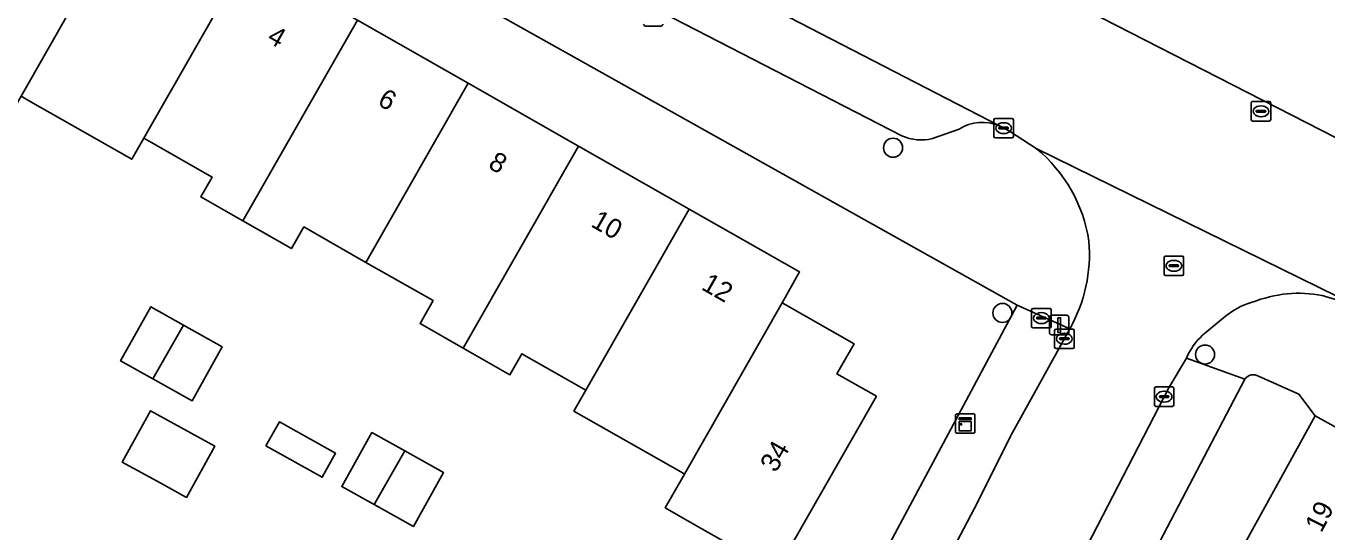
# Model space of a CAD drawing. Extents: x 160349 to 161355, y 381727 to 382854.
# Drawn here: x 160948.1 to 161014.9, y 382260.6 to 382286.6 of the extents above; entities that cross this region are included whole.
import ezdxf

# ---------------------------------------------------------------- set-up
doc = ezdxf.new("R2010")
doc.units = 0
for name, color, linetype in [('IMGEO_Boom', 7, 'Continuous'), ('IMGEO_Brandkraan', 7, 'Continuous'), ('IMGEO_Erf', 7, 'Continuous'), ('IMGEO_Kast', 7, 'Continuous'), ('IMGEO_Kolk', 7, 'Continuous'), ('IMGEO_Lichtmast', 7, 'Continuous'), ('IMGEO_Pand', 7, 'Continuous'), ('IMGEO_Pand_nummerreeks', 7, 'Continuous'), ('IMGEO_Parkeervlak_open', 7, 'Continuous'), ('IMGEO_Rijbaan_lokaal_open', 7, 'Continuous'), ('IMGEO_Rioolput', 7, 'Continuous'), ('IMGEO_Voetpad_open', 7, 'Continuous')]:
    doc.layers.add(name, color=color, linetype=linetype)

msp = doc.modelspace()

# ---------------------------------------------------------------- linework, layer by layer
at = {"layer": 'IMGEO_Boom'}
for centre in [(160992.651, 382280.362), (160998.268, 382271.874), (161008.67, 382269.741)]:
    msp.add_circle(centre, 0.489, dxfattribs=at)
at = {"layer": 'IMGEO_Brandkraan'}
for p, q in [((160999.843, 382272.112), (161000.695, 382272.112)), ((160999.768, 382271.186), (160999.768, 382272.038)), ((161000.027, 382271.606), (161000.027, 382271.618)), ((161000.465, 382271.569), (161000.067, 382271.569)), ((161000.07, 382271.655), (161000.468, 382271.655)), ((161000.256, 382271.892), (161000.281, 382271.892)), ((161000.511, 382271.618), (161000.511, 382271.606)), ((161000.769, 382272.038), (161000.769, 382271.186)), ((161000.695, 382271.112), (160999.843, 382271.112)), ((161000.279, 382271.332), (161000.254, 382271.332))]:
    msp.add_line(p, q, dxfattribs=at)
for points in [[(160999.843, 382272.112), (161000.695, 382272.112)], [(160999.768, 382271.186), (160999.768, 382272.038)], [(161000.769, 382272.038), (161000.769, 382271.186)], [(161000.695, 382271.112), (160999.843, 382271.112)]]:
    msp.add_lwpolyline(points, dxfattribs=at)
for centre, radius, start, end in [((160999.845, 382272.036), 0.0765, 91.55205, 178.44795), ((160999.845, 382272.036), 0.0765, 91.55205, 178.44795), ((161000.693, 382272.036), 0.0765, 1.55205, 88.44795), ((161000.693, 382272.036), 0.0765, 1.55205, 88.44795), ((161000.067, 382271.615), 0.0403, 85.87752, 175.75265), ((161000.064, 382271.605), 0.0366, 178.93798, 274.71019), ((161000.468, 382271.612), 0.043, 264.86636, 352.45326), ((161000.472, 382271.617), 0.0386, 1.73085, 96.63898), ((160999.845, 382271.188), 0.0765, 181.55205, 268.44795), ((160999.845, 382271.188), 0.0765, 181.55205, 268.44795), ((161000.693, 382271.188), 0.0765, 271.55205, 358.44795), ((161000.693, 382271.188), 0.0765, 271.55205, 358.44795)]:
    msp.add_arc(centre, radius, start, end, dxfattribs=at)
for centre, major_axis, ratio, start_param, end_param in [((161000.255, 382271.612), (-0.387, 0.002), 0.722429, 4.712389, 7.853982), ((161000.28, 382271.612), (-0.39, 0.002), 0.717154, 1.570796, 4.712389)]:
    msp.add_ellipse(centre, major_axis=major_axis, ratio=ratio, start_param=start_param, end_param=end_param, dxfattribs=at)
at = {"layer": 'IMGEO_Erf'}
for points in [[(160983.76, 382243.716), (160987.119, 382250), (160999.031, 382272.284), (160967.843, 382289.749), (160946.666, 382301.996), (160939.201, 382288.699), (160936.619, 382290.081), (160913.893, 382250), (160899.959, 382225.424), (160914.904, 382214.884), (160933.74, 382199.155), (160940.193, 382193.026), (160947.35, 382185.726), (160952.971, 382178.985), (160954.398, 382178.232)], [(160965.164, 382286.918), (160970.838, 382283.684), (160976.513, 382280.449), (160982.187, 382277.214), (160987.859, 382273.981), (160986.96, 382272.4), (160990.653, 382270.295), (160989.775, 382268.754), (160991.8, 382267.599), (160986.674, 382258.608), (160982.331, 382261.085), (160980.956, 382261.869), (160981.943, 382263.601), (160981.755, 382263.708), (160976.27, 382266.835), (160976.882, 382267.909), (160976.757, 382267.98), (160973.603, 382269.778), (160972.988, 382268.699), (160970.593, 382270.064), (160968.371, 382271.331), (160969.041, 382272.507), (160965.588, 382274.475), (160962.403, 382276.291), (160961.77, 382275.18), (160959.281, 382276.599), (160957.11, 382277.837), (160957.691, 382278.856), (160954.435, 382280.713), (160954.188, 382280.854), (160953.569, 382279.769), (160948.234, 382282.811), (160947.892, 382283.006)], [(161010.718, 382268.477), (161001.05, 382250), (161000, 382247.993), (160997.29, 382242.813), (160991.372, 382230.837), (160990.356, 382228.781), (160989.581, 382227.212), (160982.785, 382211.031), (160982.126, 382209.084), (160981.516, 382207.281), (160980.74, 382204.987), (160976.659, 382192.637), (160974.867, 382187.058), (160969.735, 382171.08), (160966.038, 382160.763), (160963.354, 382154.785)], [(161009.884, 382258.544), (161014.329, 382266.584), (161013.486, 382267.708), (161011.411, 382268.621)]]:
    msp.add_lwpolyline(points, dxfattribs=at)
for points in [[(160952.995, 382269.413), (160954.543, 382272.183), (160956.227, 382271.242), (160958.22, 382270.129), (160956.672, 382267.359), (160954.655, 382268.485)], [(160953.081, 382264.219), (160954.537, 382266.856), (160957.833, 382265.037), (160956.377, 382262.4), (160955.059, 382263.127)], [(160960.462, 382265.049), (160961.152, 382266.283), (160964.036, 382264.672), (160963.347, 382263.438)], [(160964.355, 382262.962), (160965.903, 382265.732), (160967.587, 382264.791), (160969.58, 382263.678), (160968.032, 382260.908), (160966.016, 382262.034)]]:
    msp.add_lwpolyline(points, close=True, dxfattribs=at)
msp.add_arc((161011.137, 382268.201), 0.502, 56.8989, 146.57824, dxfattribs=at)
at = {"layer": 'IMGEO_Kast'}
for p, q in [((160995.86, 382265.769), (160995.86, 382266.61)), ((160995.86, 382266.61), (160995.86, 382265.769)), ((160995.935, 382266.694), (160996.776, 382266.694)), ((160996.776, 382266.694), (160995.935, 382266.694)), ((160996.86, 382266.619), (160996.86, 382265.778)), ((160996.86, 382265.778), (160996.86, 382266.619)), ((160996.785, 382265.694), (160995.944, 382265.694)), ((160995.944, 382265.694), (160996.785, 382265.694))]:
    msp.add_line(p, q, dxfattribs=at)
for points in [[(160996.055, 382266.484), (160996.655, 382266.484), (160996.655, 382266.399), (160996.055, 382266.399), (160996.055, 382266.484)], [(160996.055, 382266.309), (160996.655, 382266.309), (160996.655, 382265.82), (160996.055, 382265.82), (160996.055, 382266.309)]]:
    msp.add_lwpolyline(points, dxfattribs=at)
msp.add_circle((160996.139, 382266.158), 0.0377, dxfattribs=at)
for centre, start, end in [((160995.938, 382266.616), 92.4484, 184.28452), ((160995.938, 382266.616), 92.4484, 184.28452), ((160996.782, 382266.616), 2.4484, 94.28452), ((160996.782, 382266.616), 2.4484, 94.28452), ((160995.938, 382265.772), 182.4484, 274.28452), ((160995.938, 382265.772), 182.4484, 274.28452), ((160996.782, 382265.772), 272.4484, 4.28452), ((160996.782, 382265.772), 272.4484, 4.28452)]:
    msp.add_arc(centre, 0.0779, start, end, dxfattribs=at)
at = {"layer": 'IMGEO_Kolk'}
for p, q in [((160997.829, 382280.942), (160997.829, 382281.794)), ((160997.904, 382281.868), (160998.756, 382281.868)), ((160998.317, 382281.648), (160998.342, 382281.648)), ((160998.83, 382281.794), (160998.83, 382280.942)), ((160998.756, 382280.868), (160997.904, 382280.868)), ((160998.088, 382281.362), (160998.088, 382281.374)), ((160998.526, 382281.325), (160998.128, 382281.325)), ((160998.131, 382281.411), (160998.529, 382281.411)), ((160998.34, 382281.088), (160998.315, 382281.088)), ((160998.572, 382281.374), (160998.572, 382281.362)), ((161000.947, 382270.125), (161000.947, 382270.977)), ((161001.022, 382271.051), (161001.874, 382271.051)), ((161001.435, 382270.831), (161001.46, 382270.831)), ((161001.948, 382270.977), (161001.948, 382270.125)), ((161001.206, 382270.545), (161001.206, 382270.557)), ((161001.644, 382270.508), (161001.246, 382270.508)), ((161001.249, 382270.594), (161001.647, 382270.594)), ((161001.458, 382270.271), (161001.433, 382270.271)), ((161001.69, 382270.557), (161001.69, 382270.545)), ((161001.874, 382270.051), (161001.022, 382270.051)), ((161006.068, 382267.151), (161006.068, 382268.003)), ((161006.143, 382268.077), (161006.995, 382268.077)), ((161006.327, 382267.571), (161006.327, 382267.583)), ((161006.765, 382267.534), (161006.367, 382267.534)), ((161006.37, 382267.62), (161006.768, 382267.62)), ((161006.556, 382267.857), (161006.581, 382267.857)), ((161006.811, 382267.583), (161006.811, 382267.571)), ((161007.069, 382268.003), (161007.069, 382267.151)), ((161006.995, 382267.077), (161006.143, 382267.077)), ((161006.579, 382267.297), (161006.554, 382267.297))]:
    msp.add_line(p, q, dxfattribs=at)
for points in [[(160997.829, 382280.942), (160997.829, 382281.794)], [(160997.904, 382281.868), (160998.756, 382281.868)], [(160998.83, 382281.794), (160998.83, 382280.942)], [(160998.756, 382280.868), (160997.904, 382280.868)], [(161000.947, 382270.125), (161000.947, 382270.977)], [(161001.022, 382271.051), (161001.874, 382271.051)], [(161001.948, 382270.977), (161001.948, 382270.125)], [(161001.874, 382270.051), (161001.022, 382270.051)], [(161006.068, 382267.151), (161006.068, 382268.003)], [(161006.143, 382268.077), (161006.995, 382268.077)], [(161007.069, 382268.003), (161007.069, 382267.151)], [(161006.995, 382267.077), (161006.143, 382267.077)]]:
    msp.add_lwpolyline(points, dxfattribs=at)
for centre, radius, start, end in [((160997.906, 382281.792), 0.0765, 91.55205, 178.44795), ((160997.906, 382281.792), 0.0765, 91.55205, 178.44795), ((160998.754, 382281.792), 0.0765, 1.55205, 88.44795), ((160998.754, 382281.792), 0.0765, 1.55205, 88.44795), ((160997.906, 382280.944), 0.0765, 181.55205, 268.44795), ((160997.906, 382280.944), 0.0765, 181.55205, 268.44795), ((160998.128, 382281.371), 0.0403, 85.87752, 175.75265), ((160998.125, 382281.361), 0.0366, 178.93798, 274.71019), ((160998.529, 382281.368), 0.043, 264.86636, 352.45326), ((160998.533, 382281.373), 0.0386, 1.73085, 96.63898), ((160998.754, 382280.944), 0.0765, 271.55205, 358.44795), ((160998.754, 382280.944), 0.0765, 271.55205, 358.44795), ((161001.024, 382270.975), 0.0765, 91.55205, 178.44795), ((161001.024, 382270.975), 0.0765, 91.55205, 178.44795), ((161001.872, 382270.975), 0.0765, 1.55205, 88.44795), ((161001.872, 382270.975), 0.0765, 1.55205, 88.44795), ((161001.024, 382270.127), 0.0765, 181.55205, 268.44795), ((161001.024, 382270.127), 0.0765, 181.55205, 268.44795), ((161001.246, 382270.554), 0.0403, 85.87752, 175.75265), ((161001.243, 382270.544), 0.0366, 178.93798, 274.71019), ((161001.647, 382270.551), 0.043, 264.86636, 352.45326), ((161001.651, 382270.556), 0.0386, 1.73085, 96.63898), ((161001.872, 382270.127), 0.0765, 271.55205, 358.44795), ((161001.872, 382270.127), 0.0765, 271.55205, 358.44795), ((161006.145, 382268.001), 0.0765, 91.55205, 178.44795), ((161006.145, 382268.001), 0.0765, 91.55205, 178.44795), ((161006.367, 382267.58), 0.0403, 85.87752, 175.75265), ((161006.364, 382267.57), 0.0366, 178.93798, 274.71019), ((161006.768, 382267.577), 0.043, 264.86636, 352.45326), ((161006.772, 382267.582), 0.0386, 1.73085, 96.63898), ((161006.993, 382268.001), 0.0765, 1.55205, 88.44795), ((161006.993, 382268.001), 0.0765, 1.55205, 88.44795), ((161006.145, 382267.153), 0.0765, 181.55205, 268.44795), ((161006.145, 382267.153), 0.0765, 181.55205, 268.44795), ((161006.993, 382267.153), 0.0765, 271.55205, 358.44795), ((161006.993, 382267.153), 0.0765, 271.55205, 358.44795)]:
    msp.add_arc(centre, radius, start, end, dxfattribs=at)
for centre, major_axis, ratio, start_param, end_param in [((160998.316, 382281.368), (-0.387, 0.002), 0.722429, 4.712389, 7.853982), ((160998.341, 382281.368), (-0.39, 0.002), 0.717154, 1.570796, 4.712389), ((161001.434, 382270.551), (-0.387, 0.002), 0.722429, 4.712389, 7.853982), ((161001.459, 382270.551), (-0.39, 0.002), 0.717154, 1.570796, 4.712389), ((161006.555, 382267.577), (-0.387, 0.002), 0.722429, 4.712389, 7.853982), ((161006.58, 382267.577), (-0.39, 0.002), 0.717154, 1.570796, 4.712389)]:
    msp.add_ellipse(centre, major_axis=major_axis, ratio=ratio, start_param=start_param, end_param=end_param, dxfattribs=at)
at = {"layer": 'IMGEO_Lichtmast'}
for p, q in [((160980.735, 382286.612), (160979.945, 382286.612)), ((160979.945, 382286.612), (160980.735, 382286.612)), ((161000.684, 382270.855), (161000.684, 382271.655)), ((161000.684, 382271.655), (161000.684, 382270.855)), ((161000.784, 382271.755), (161001.574, 382271.755)), ((161001.574, 382271.755), (161000.784, 382271.755)), ((161001.674, 382271.655), (161001.674, 382270.855)), ((161001.674, 382270.855), (161001.674, 382271.655)), ((161001.574, 382270.755), (161000.784, 382270.755)), ((161000.784, 382270.755), (161001.574, 382270.755))]:
    msp.add_line(p, q, dxfattribs=at)
msp.add_lwpolyline([(161001.104, 382271.63), (161001.254, 382271.63), (161001.254, 382270.88), (161001.104, 382270.88), (161001.104, 382271.63)], dxfattribs=at)
for centre, start, end in [((160979.945, 382286.712), 180, 270), ((160979.945, 382286.712), 180, 270), ((160980.735, 382286.712), 270, 0), ((160980.735, 382286.712), 270, 0), ((161000.784, 382271.655), 90, 180), ((161000.784, 382271.655), 90, 180), ((161001.574, 382271.655), 0, 90), ((161001.574, 382271.655), 360, 90), ((161000.784, 382270.855), 180, 270), ((161000.784, 382270.855), 180, 270), ((161001.574, 382270.855), 270, 0), ((161001.574, 382270.855), 270, 0)]:
    msp.add_arc(centre, 0.1, start, end, dxfattribs=at)
at = {"layer": 'IMGEO_Pand'}
for points in [[(160952.966, 382291.903), (160949.178, 382294.062), (160948.288, 382292.502), (160946.342, 382293.611), (160940.859, 382283.993), (160943.585, 382282.439), (160943.881, 382282.917), (160946.87, 382281.213), (160947.892, 382283.006)], [(160959.489, 382290.153), (160953.813, 382293.389), (160952.966, 382291.903), (160947.892, 382283.006), (160948.234, 382282.811), (160953.569, 382279.769), (160954.188, 382280.854)], [(160965.164, 382286.918), (160959.489, 382290.153), (160954.188, 382280.854), (160954.435, 382280.713), (160957.691, 382278.856), (160957.11, 382277.837), (160959.281, 382276.599)], [(160965.164, 382286.918), (160959.281, 382276.599), (160961.77, 382275.18), (160962.403, 382276.291), (160965.588, 382274.475), (160970.838, 382283.684)], [(160976.513, 382280.449), (160970.838, 382283.684), (160965.588, 382274.475), (160969.041, 382272.507), (160968.371, 382271.331), (160970.593, 382270.064)], [(160982.187, 382277.214), (160976.513, 382280.449), (160970.593, 382270.064), (160972.988, 382268.699), (160973.603, 382269.778), (160976.757, 382267.98), (160976.882, 382267.909)], [(160986.96, 382272.4), (160987.859, 382273.981), (160982.187, 382277.214), (160976.882, 382267.909), (160976.27, 382266.835), (160981.755, 382263.708), (160981.943, 382263.601)], [(160954.655, 382268.485), (160956.227, 382271.242), (160954.543, 382272.183), (160952.995, 382269.413)], [(160991.8, 382267.599), (160989.775, 382268.754), (160990.653, 382270.295), (160986.96, 382272.4), (160981.943, 382263.601), (160980.956, 382261.869), (160982.331, 382261.085), (160986.674, 382258.608)], [(160954.655, 382268.485), (160956.672, 382267.359), (160958.22, 382270.129), (160956.227, 382271.242)], [(160957.833, 382265.037), (160954.537, 382266.856), (160953.081, 382264.219), (160955.059, 382263.127), (160956.377, 382262.4)], [(160960.462, 382265.049), (160963.347, 382263.438), (160964.036, 382264.672), (160961.152, 382266.283)], [(161024.625, 382260.892), (161014.329, 382266.584), (161009.884, 382258.544), (161009.932, 382258.519), (161019.208, 382253.814), (161020.646, 382256.64), (161021.916, 382255.993)], [(160966.016, 382262.034), (160967.587, 382264.791), (160965.903, 382265.732), (160964.355, 382262.962)], [(160966.016, 382262.034), (160968.032, 382260.908), (160969.58, 382263.678), (160967.587, 382264.791)]]:
    msp.add_lwpolyline(points, close=True, dxfattribs=at)
at = {"layer": 'IMGEO_Parkeervlak_open'}
for points in [[(160998.118, 382281.479), (160978.184, 382291.798), (160975.741, 382293.063), (160952.254, 382305.221)], [(160954.677, 382300.798), (160974.935, 382290.345), (160975.866, 382292.149), (160977.003, 382291.562), (160976.072, 382289.757), (160993.102, 382280.969)], [(160994.677, 382280.829), (160996.045, 382281.31)]]:
    msp.add_lwpolyline(points, dxfattribs=at)
for centre, radius, start, end in [((160997.236, 382279.496), 2.17, 66.03014, 123.29125), ((160994.099, 382283.257), 2.496, 246.45466, 283.38612)]:
    msp.add_arc(centre, radius, start, end, dxfattribs=at)
at = {"layer": 'IMGEO_Rijbaan_lokaal_open'}
for points in [[(161002.583, 382287.432), (161001.819, 382287.83), (161000, 382288.778), (160981.577, 382298.373), (160978.184, 382291.798), (160998.118, 382281.479), (160998.634, 382281.212), (161000, 382280.323), (161016.444, 382272.241), (161019.32, 382270.57), (161025.658, 382267.377), (161031.592, 382264.239), (161035.746, 382271.895), (161020.078, 382278.447)], [(161002.583, 382287.432), (161019.106, 382278.967)], [(161019.106, 382278.967), (161002.583, 382287.432)], [(161014.689, 382272.773), (161016.444, 382272.241), (161000, 382280.323)], [(161008.543, 382270.731), (161009.624, 382271.631)], [(161001.724, 382271.052), (161000, 382267.933), (160998.789, 382265.742), (160996.81, 382261.813), (160993.633, 382255.762), (160991.886, 382252.343), (160991.362, 382251.317), (160990.647, 382250), (160990.118, 382249.025), (160989.869, 382248.566), (160988.024, 382245.008), (160986.613, 382242.205), (160984.499, 382237.775), (160981.916, 382232.21), (160980.069, 382228.082), (160978.591, 382224.931)], [(160997.419, 382249.852), (160997.495, 382250), (161000, 382254.851), (161006.824, 382268.068), (161007.716, 382269.561)]]:
    msp.add_lwpolyline(points, dxfattribs=at)
for centre, radius, start, end in [((160995.17, 382274.421), 7.626, 8.61726, 50.70121), ((160994.858, 382274.916), 7.879, 330.62995, 4.71612), ((161013.807, 382265.143), 7.775, 96.77994, 110.49949), ((161013.463, 382266.369), 6.52, 79.16187, 95.04982), ((161012.226, 382268.59), 4.002, 106.58186, 130.55654), ((161010.84, 382268.23), 3.395, 132.56566, 156.92613)]:
    msp.add_arc(centre, radius, start, end, dxfattribs=at)
at = {"layer": 'IMGEO_Rioolput'}
for p, q in [((161011.039, 382281.806), (161011.039, 382282.658)), ((161011.114, 382282.732), (161011.966, 382282.732)), ((161011.298, 382282.226), (161011.298, 382282.238)), ((161011.736, 382282.189), (161011.338, 382282.189)), ((161011.341, 382282.275), (161011.739, 382282.275)), ((161011.527, 382282.512), (161011.552, 382282.512)), ((161011.782, 382282.238), (161011.782, 382282.226)), ((161012.04, 382282.658), (161012.04, 382281.806)), ((161011.966, 382281.732), (161011.114, 382281.732)), ((161011.55, 382281.952), (161011.525, 382281.952)), ((161006.643, 382274.797), (161007.495, 382274.797)), ((161006.568, 382273.871), (161006.568, 382274.723)), ((161006.827, 382274.291), (161006.827, 382274.303)), ((161007.265, 382274.254), (161006.867, 382274.254)), ((161006.87, 382274.34), (161007.268, 382274.34)), ((161007.056, 382274.577), (161007.081, 382274.577)), ((161007.311, 382274.303), (161007.311, 382274.291)), ((161007.569, 382274.723), (161007.569, 382273.871)), ((161007.495, 382273.797), (161006.643, 382273.797)), ((161007.079, 382274.017), (161007.054, 382274.017))]:
    msp.add_line(p, q, dxfattribs=at)
for points in [[(161011.039, 382281.806), (161011.039, 382282.658)], [(161011.114, 382282.732), (161011.966, 382282.732)], [(161012.04, 382282.658), (161012.04, 382281.806)], [(161011.966, 382281.732), (161011.114, 382281.732)], [(161006.643, 382274.797), (161007.495, 382274.797)], [(161006.568, 382273.871), (161006.568, 382274.723)], [(161007.569, 382274.723), (161007.569, 382273.871)], [(161007.495, 382273.797), (161006.643, 382273.797)]]:
    msp.add_lwpolyline(points, dxfattribs=at)
for centre, radius, start, end in [((161011.116, 382282.656), 0.0765, 91.55205, 178.44795), ((161011.116, 382282.656), 0.0765, 91.55205, 178.44795), ((161011.338, 382282.235), 0.0403, 85.87752, 175.75265), ((161011.335, 382282.225), 0.0366, 178.93798, 274.71019), ((161011.739, 382282.232), 0.043, 264.86636, 352.45326), ((161011.743, 382282.237), 0.0386, 1.73085, 96.63898), ((161011.964, 382282.656), 0.0765, 1.55205, 88.44795), ((161011.964, 382282.656), 0.0765, 1.55205, 88.44795), ((161011.116, 382281.808), 0.0765, 181.55205, 268.44795), ((161011.116, 382281.808), 0.0765, 181.55205, 268.44795), ((161011.964, 382281.808), 0.0765, 271.55205, 358.44795), ((161011.964, 382281.808), 0.0765, 271.55205, 358.44795), ((161006.645, 382274.721), 0.0765, 91.55205, 178.44795), ((161006.645, 382274.721), 0.0765, 91.55205, 178.44795), ((161007.493, 382274.721), 0.0765, 1.55205, 88.44795), ((161007.493, 382274.721), 0.0765, 1.55205, 88.44795), ((161006.867, 382274.3), 0.0403, 85.87752, 175.75265), ((161006.864, 382274.29), 0.0366, 178.93798, 274.71019), ((161007.268, 382274.297), 0.043, 264.86636, 352.45326), ((161007.272, 382274.302), 0.0386, 1.73085, 96.63898), ((161006.645, 382273.873), 0.0765, 181.55205, 268.44795), ((161006.645, 382273.873), 0.0765, 181.55205, 268.44795), ((161007.493, 382273.873), 0.0765, 271.55205, 358.44795), ((161007.493, 382273.873), 0.0765, 271.55205, 358.44795)]:
    msp.add_arc(centre, radius, start, end, dxfattribs=at)
for centre, major_axis, ratio, start_param, end_param in [((161011.526, 382282.232), (-0.387, 0.002), 0.722429, 4.712389, 7.853982), ((161011.551, 382282.232), (-0.39, 0.002), 0.717154, 1.570796, 4.712389), ((161007.055, 382274.297), (-0.387, 0.002), 0.722429, 4.712389, 7.853982), ((161007.08, 382274.297), (-0.39, 0.002), 0.717154, 1.570796, 4.712389)]:
    msp.add_ellipse(centre, major_axis=major_axis, ratio=ratio, start_param=start_param, end_param=end_param, dxfattribs=at)
at = {"layer": 'IMGEO_Voetpad_open'}
for points in [[(160949.08, 382306.184), (160946.666, 382301.996), (160967.843, 382289.749), (160999.031, 382272.284), (161001.724, 382271.052)], [(160993.102, 382280.969), (160976.072, 382289.757), (160977.003, 382291.562), (160975.866, 382292.149), (160974.935, 382290.345), (160954.677, 382300.798)], [(160998.634, 382281.212), (160998.118, 382281.479)], [(160996.045, 382281.31), (160994.677, 382280.829)], [(161000, 382280.323), (160998.634, 382281.212)], [(161055.733, 382251.819), (161049.423, 382255.063), (161049.189, 382254.622), (161039.86, 382259.512), (161040.094, 382259.953), (161034.134, 382262.947), (161032.15, 382263.944), (161031.592, 382264.239), (161025.658, 382267.377), (161019.32, 382270.57), (161016.444, 382272.241), (161014.689, 382272.773)], [(160978.591, 382224.931), (160980.069, 382228.082), (160981.916, 382232.21), (160984.499, 382237.775), (160986.613, 382242.205), (160988.024, 382245.008), (160989.869, 382248.566), (160990.118, 382249.025), (160989.659, 382249.227), (160990.071, 382250), (160991.433, 382252.554), (160991.886, 382252.343), (160993.633, 382255.762), (160996.81, 382261.813), (160998.789, 382265.742), (161000, 382267.933), (161001.724, 382271.052), (160999.031, 382272.284), (160987.119, 382250), (160983.76, 382243.716), (160980.003, 382235.908), (160972.505, 382218.123), (160970.065, 382211.776), (160966.122, 382199.939)], [(161009.624, 382271.631), (161008.543, 382270.731)], [(160997.29, 382242.813), (161000, 382247.993), (161001.05, 382250), (161010.718, 382268.477), (161007.716, 382269.561), (161006.824, 382268.068), (161000, 382254.851), (160997.495, 382250), (160997.419, 382249.852)], [(161007.716, 382269.561), (161010.718, 382268.477)], [(161011.411, 382268.621), (161013.486, 382267.708), (161014.329, 382266.584), (161024.625, 382260.892), (161028.769, 382258.589), (161036.639, 382254.021), (161043.387, 382250), (161065.416, 382238.763), (161079.811, 382231.42)]]:
    msp.add_lwpolyline(points, dxfattribs=at)
for centre, radius, start, end in [((160997.236, 382279.496), 2.17, 66.03014, 123.29125), ((160994.099, 382283.257), 2.496, 246.45466, 283.38612), ((160995.17, 382274.421), 7.626, 8.61726, 50.70121), ((160994.858, 382274.916), 7.879, 330.62995, 4.71612), ((161013.807, 382265.143), 7.775, 96.77994, 110.49949), ((161013.463, 382266.369), 6.52, 79.16187, 95.04982), ((161012.226, 382268.59), 4.002, 106.58186, 130.55654), ((161010.84, 382268.23), 3.395, 132.56566, 156.92613), ((161011.137, 382268.201), 0.502, 56.8989, 146.57824)]:
    msp.add_arc(centre, radius, start, end, dxfattribs=at)

# ---------------------------------------------------------------- texts
at = {"layer": 'IMGEO_Pand_nummerreeks'}
for s, rotation, p in [('4', 330.31506, (160960.46, 382285.825)), ('6', 330.3146, (160966.135, 382282.59)), ('8', 330.3146, (160971.813, 382279.353)), ('10', 330.31506, (160977.086, 382276.346)), ('12', 330.31506, (160982.756, 382273.114)), ('34', 60.30954, (160986.639, 382263.633)), ('19', 63.03109, (161014.642, 382260.543))]:
    msp.add_text(s, height=1, rotation=rotation, dxfattribs=at).set_placement(p)

doc.saveas('drawing.dxf')
